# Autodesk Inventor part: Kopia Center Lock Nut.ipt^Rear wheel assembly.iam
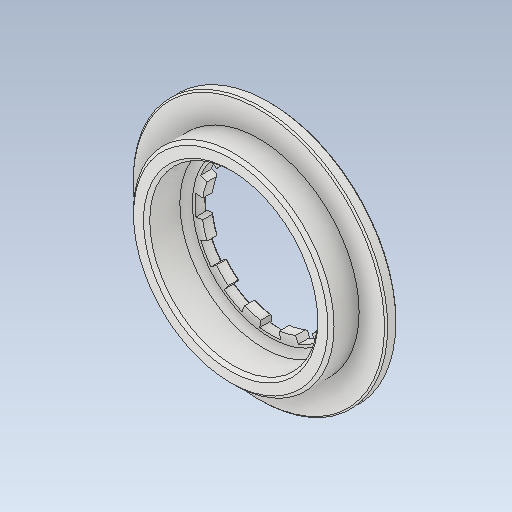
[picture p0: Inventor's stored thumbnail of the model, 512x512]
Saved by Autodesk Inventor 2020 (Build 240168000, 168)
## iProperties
Created: 2017-09
Part Number: Kopia Center Lock Nut.ipt^Rear wheel assembly.iam
Material: Ogólny
Document SubType Name: Modeling
Designer: Tomasz
Density: 1 g/cm^3
Appearance: Domyślna
Sending System: SolidWorks 2017
Last Author: Tomasz
Last Saved: 2017-09-11
Author: Tomasz
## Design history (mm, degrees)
feature "Center Lock Nut.ipt"
node "Bryła1"
